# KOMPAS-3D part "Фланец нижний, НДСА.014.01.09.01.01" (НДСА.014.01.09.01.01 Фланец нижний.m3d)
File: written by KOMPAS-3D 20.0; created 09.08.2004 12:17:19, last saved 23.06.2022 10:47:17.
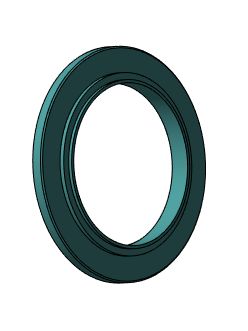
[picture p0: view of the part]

Document properties: Автор: Устинов А.В.; Организация: Эсто-вакуум; Полное имя файла: C:\Users\cherbakova\Desktop\PLM\НДСА.014.01.09.01.01 Фланец нижний.m3d

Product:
- Part/product: Фланец нижний  | designation НДСА.014.01.09.01.01
    Материал: Сталь 20 ГОСТ 1050-88 (density 7859 kg/m3)
    Масса: 2.34227
    additional columns: <item xmlns="http://appius.ru/pdm" xmlns:xs="http://www.w3.org/2001/XMLSchema" x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; <item xmlns="http://appius.ru/pdm" xmlns:xs="http://www.w3.org/2001/XMLSchema" x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; <item xmlns="http://appius.ru/pdm" xmlns:xs="http://www.w3.org/2001/XMLSchema" x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; <item xmlns="http://appius.ru/pdm" xmlns:xs="http://www.w3.org/2001/XMLSchema" x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; <item xmlns="http://appius.ru/pdm" xmlns:xs="http://www.w3.org/2001/XMLSchema" x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; <item xmlns="http://appius.ru/pdm" xmlns:xs="http://www.w3.org/2001/XMLSchema" x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
    source file: НДСА.014.01.09.01.01 Фланец нижний.CDW

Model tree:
1. Плоскость XY
2. Плоскость ZX
3. Плоскость ZY
4. Начало координат
5. Эскиз:1
6. Операция выдавливания:1
     Расстояние 1 = 12
7. Эскиз:2  (labels: Операция выдавливания:1; Операция выдавливания:1)
8. Приклеить элемент выдавливания:1
     Расстояние 1 = 5
9. Эскиз:3  (labels: Приклеить элемент выдавливания:1; Приклеить элемент выдавливания:1)
10. Приклеить элемент выдавливания:2
     Расстояние 1 = 4
11. Эскиз:4  (labels: Приклеить элемент выдавливания:2; Приклеить элемент выдавливания:2)
12. Вырезать элемент выдавливания:1
     Расстояние 2 = 21
13. Фаска:2  (labels: Операция выдавливания:1; Сталь 20 ГОСТ 1050-88)
     Угол = 45; Длина 1 = 1.5; Длина 2 = 1.5

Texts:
  НДСА.014.01.09.01.01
